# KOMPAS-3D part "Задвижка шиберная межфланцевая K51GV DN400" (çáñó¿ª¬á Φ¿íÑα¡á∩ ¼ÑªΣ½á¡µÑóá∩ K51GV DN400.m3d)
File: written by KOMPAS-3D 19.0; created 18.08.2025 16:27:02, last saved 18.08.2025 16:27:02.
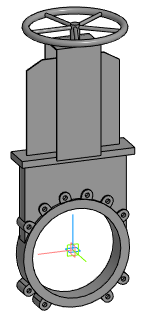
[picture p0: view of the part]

Document properties: Автор: Евгений; Полное имя файла: E:\Dendor Работа Сачек\3D для проектировщиков\2.4 Тип K51GV. Задвижка шиберная межфланцевая\stp_Задвижка шиберная K51GV DN50-400 с маховиком\Задвижка шиберная межфланцевая K51GV DN400.m3d

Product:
- Part/product: Задвижка шиберная межфланцевая K51GV DN400

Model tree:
1. Операция без истории:1  (labels: Задвижка шиберная межфланцевая K51GV DN400)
